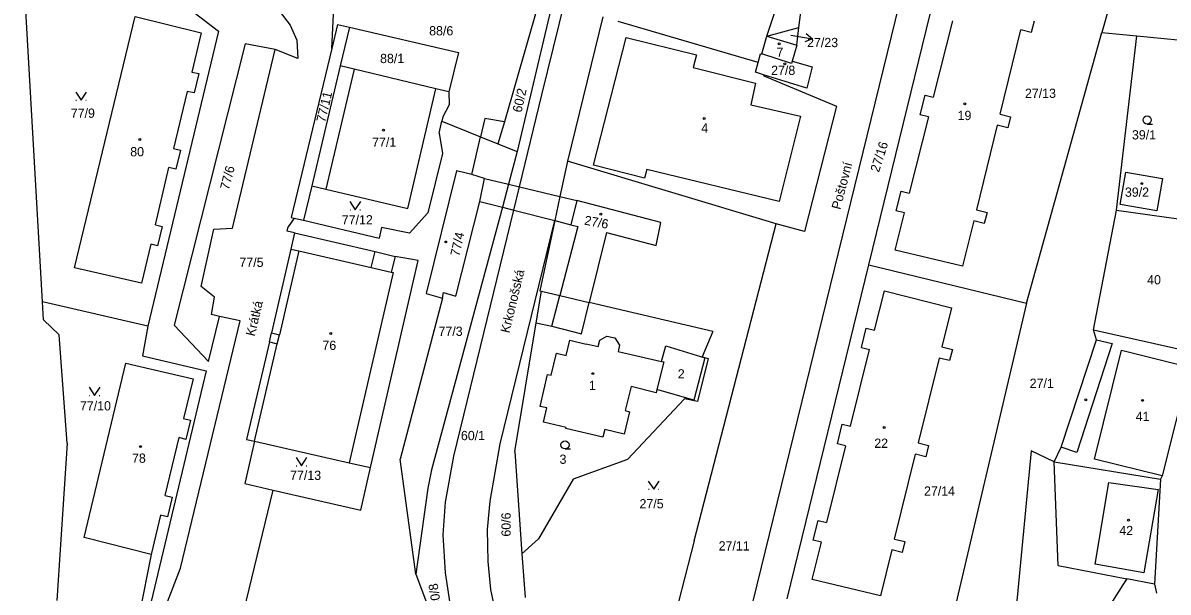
# Model space of a CAD drawing. Extents: x -670359 to -668019, y -978807 to -976674.
# Drawn here: x -670340.4 to -670130.3, y -977711.4 to -977606.8 of the extents above; entities that cross this region are included whole.
import ezdxf

# ---------------------------------------------------------------- set-up
doc = ezdxf.new("R2010")
doc.units = 0
for name, color, linetype in [('Hranice kat_území', 7, 'Continuous'), ('Hranice parcel', 7, 'Continuous'), ('Parcelní čísla', 7, 'Continuous'), ('Pop  PČ popisy', 7, 'Continuous'), ('Vnitřní kresba', 7, 'Continuous'), ('Značky budov', 7, 'Continuous'), ('Značky kultur', 7, 'Continuous')]:
    doc.layers.add(name, color=color, linetype=linetype)

msp = doc.modelspace()

# ---------------------------------------------------------------- linework, layer by layer
at = {"layer": 'Hranice kat_území'}
for points in [[(-670336.85, -977658.05), (-670340.44, -977594.85)], [(-670336.66, -977661.37), (-670336.85, -977658.05)], [(-670333.8, -977664.11), (-670336.66, -977661.37)], [(-670332.34, -977684.03), (-670333.8, -977664.11)], [(-670332.34, -977684.03), (-670334.21, -977712.94)]]:
    msp.add_lwpolyline(points, dxfattribs=at)
at = {"layer": 'Hranice parcel'}
for points in [[(-670249.31, -977636.91), (-670245.2, -977620.01), (-670240.92, -977602.66), (-670233.02, -977570.23), (-670231.23, -977562.51), (-670223.3, -977530.56), (-670219.23, -977513.75), (-670216.62, -977503.27), (-670213.37, -977489.17), (-670213.69, -977478.11)], [(-670163.89, -977539.01), (-670213.94, -977743.56)], [(-670203.93, -977609.27), (-670201.17, -977600.83), (-670198.43, -977589.2), (-670197.97, -977587.25)], [(-670185.19, -977651.24), (-670170.41, -977590.62)], [(-670198.01, -977607.66), (-670196.15, -977592.93)], [(-670139.52, -977598.15), (-670142.41, -977608.56)], [(-670283.76, -977611.51), (-670283.19, -977600.11)], [(-670311.4, -977603.07), (-670304.57, -977608.35)], [(-670293.42, -977604.61), (-670291.41, -977607.22)], [(-670245.98, -977603.86), (-670252.06, -977625.01)], [(-670243.58, -977604.27), (-670249.7, -977630.46)], [(-670330.99, -977651.81), (-670319.86, -977605.66)], [(-670319.86, -977605.66), (-670307.72, -977608.63)], [(-670291.41, -977607.22), (-670290.19, -977609.96)], [(-670282.7, -977607.08), (-670283.76, -977611.51)], [(-670282.7, -977607.08), (-670280.5, -977607.59)], [(-670280.5, -977607.59), (-670282.2, -977614.71)], [(-670280.5, -977607.59), (-670260.47, -977612.22)], [(-670233.99, -977605.7), (-670240.51, -977632.21)], [(-670205.49, -977614.1), (-670231.18, -977606.53)], [(-670203.93, -977609.27), (-670198.01, -977607.66)], [(-670198.42, -977610.91), (-670198.01, -977607.66)], [(-670169.86, -977606.42), (-670173.36, -977620.47)], [(-670154.87, -977606.52), (-670155.37, -977608.55)], [(-670304.57, -977608.35), (-670317.49, -977662.51)], [(-670307.72, -977608.63), (-670309.43, -977615.83)], [(-670204.8, -977612.5), (-670203.93, -977609.27)], [(-670203.93, -977609.27), (-670198.42, -977610.91)], [(-670161.11, -977623.58), (-670157.3, -977608.07)], [(-670155.37, -977608.55), (-670157.3, -977608.07)], [(-670156.24, -977658.3), (-670142.41, -977608.56)], [(-670142.41, -977608.56), (-670135.99, -977609.18)], [(-670139.74, -977641.23), (-670135.99, -977609.18)], [(-670135.99, -977609.18), (-670120.96, -977610.65)], [(-670301.97, -977644.5), (-670294.13, -977611.68)], [(-670289.99, -977613.35), (-670294.13, -977611.68)], [(-670283.76, -977611.51), (-670291.18, -977642.54)], [(-670290.19, -977609.96), (-670289.99, -977613.35)], [(-670198.42, -977610.91), (-670199.28, -977613.85)], [(-670260.47, -977612.22), (-670262.27, -977619.5)], [(-670205.49, -977614.1), (-670205.06, -977612.48)], [(-670205.06, -977612.48), (-670204.8, -977612.5)], [(-670199.4, -977614.26), (-670204.8, -977612.5)], [(-670199.28, -977613.85), (-670195.6, -977614.87), (-670196.57, -977618.81), (-670204.52, -977616.32)], [(-670199.28, -977613.85), (-670199.4, -977614.26)], [(-670309.43, -977615.83), (-670308.17, -977616.13)], [(-670282.2, -977614.71), (-670287.43, -977636.75)], [(-670279.63, -977615.33), (-670282.2, -977614.71)], [(-670264.66, -977618.94), (-670279.63, -977615.33)], [(-670204.52, -977616.32), (-670205.96, -977615.87), (-670205.49, -977614.1)], [(-670308.17, -977616.13), (-670309.02, -977619.68)], [(-670204.52, -977616.32), (-670204.46, -977616.54)], [(-670204.46, -977616.54), (-670191.14, -977622.08)], [(-670310.28, -977619.38), (-670312.79, -977629.87)], [(-670309.02, -977619.68), (-670310.28, -977619.38)], [(-670269.78, -977640.91), (-670264.66, -977618.94)], [(-670262.27, -977619.5), (-670264.66, -977618.94)], [(-670262.27, -977619.5), (-670262.23, -977621.89)], [(-670175.76, -977623.67), (-670174.87, -977620.1)], [(-670174.87, -977620.1), (-670173.36, -977620.47)], [(-670262.23, -977621.89), (-670263.37, -977624.05)], [(-670191.14, -977622.08), (-670196.99, -977645.15)], [(-670263.37, -977624.05), (-670263.56, -977624.87)], [(-670174.25, -977624.04), (-670177.76, -977638.11)], [(-670174.25, -977624.04), (-670175.76, -977623.67)], [(-670161.11, -977623.58), (-670159.18, -977624.06)], [(-670159.18, -977624.06), (-670159.68, -977626.09)], [(-670264.06, -977627.06), (-670263.56, -977624.87)], [(-670263.56, -977624.87), (-670256.44, -977627.73)], [(-670252.06, -977625.01), (-670253.29, -977629)], [(-670161.61, -977625.61), (-670165.43, -977641.15)], [(-670159.68, -977626.09), (-670161.61, -977625.61)], [(-670264.06, -977627.06), (-670263.45, -977630.78)], [(-670258.05, -977634.65), (-670256.44, -977627.73)], [(-670256.44, -977627.73), (-670253.29, -977629)], [(-670312.79, -977629.87), (-670311.52, -977630.18)], [(-670311.52, -977630.18), (-670312.36, -977633.7)], [(-670263.45, -977630.78), (-670266.1, -977641.73)], [(-670253.29, -977629), (-670249.7, -977630.46)], [(-670249.7, -977630.46), (-670251.31, -977636.43)], [(-670240.51, -977632.21), (-670241.88, -977638.68)], [(-670202.18, -977643.75), (-670240.51, -977632.21)], [(-670316.13, -977643.91), (-670313.63, -977633.4)], [(-670312.36, -977633.7), (-670313.63, -977633.4)], [(-670260.84, -977633.99), (-670266.45, -977656.5)], [(-670258.05, -977634.65), (-670260.84, -977633.99)], [(-670255.73, -977635.38), (-670258.05, -977634.65)], [(-670132.33, -977641.31), (-670139.05, -977640.15), (-670138.03, -977634.22), (-670131.31, -977635.37), (-670132.33, -977641.31)], [(-670287.43, -977636.75), (-670288.94, -977643.07)], [(-670287.43, -977636.75), (-670284.82, -977637.36)], [(-670256.56, -977639.61), (-670255.73, -977635.38)], [(-670251.31, -977636.43), (-670252.45, -977640.66)], [(-670250.36, -977641.2), (-670249.31, -977636.91)], [(-670284.82, -977637.36), (-670269.78, -977640.91)], [(-670241.88, -977638.68), (-670242.83, -977643.13)], [(-670180.16, -977641.34), (-670179.27, -977637.73)], [(-670179.27, -977637.73), (-670177.76, -977638.11)], [(-670252.45, -977640.66), (-670265.48, -977688.9)], [(-670228.39, -977798.54), (-670235.68, -977780.88), (-670248.21, -977752.09), (-670257.66, -977728.06), (-670261.88, -977714.27), (-670262.87, -977707.81), (-670263.3, -977700.83), (-670262.9, -977694.87), (-670261.36, -977686.41), (-670250.36, -977641.2)], [(-670261.01, -977657.02), (-670256.56, -977639.61)], [(-670238.8, -977639.42), (-670239.87, -977643.89)], [(-670223.38, -977643.45), (-670238.8, -977639.42)], [(-670165.43, -977641.15), (-670163.5, -977641.63)], [(-670143.98, -977663.19), (-670139.74, -977641.23)], [(-670139.74, -977641.23), (-670121.83, -977643.75)], [(-670290.67, -977642.66), (-670291.73, -977644.25)], [(-670291.18, -977642.54), (-670290.67, -977642.66)], [(-670290.67, -977642.66), (-670288.94, -977643.07)], [(-670288.94, -977643.07), (-670275.07, -977646.34)], [(-670266.1, -977641.73), (-670269.49, -977645.42)], [(-670183.39, -977889.81), (-670193.56, -977862.25), (-670201.26, -977845.22), (-670205.62, -977834.5), (-670231.98, -977771.32), (-670242.71, -977745.05), (-670249.53, -977728.04), (-670253.85, -977714.41), (-670254.54, -977710.9), (-670255.07, -977705.75), (-670255.17, -977699.87), (-670254.7, -977694.67), (-670252.82, -977684.15), (-670242.83, -977643.13)], [(-670242.83, -977643.13), (-670245.56, -977656.01)], [(-670180.36, -977648.54), (-670178.66, -977641.71)], [(-670178.66, -977641.71), (-670180.16, -977641.34)], [(-670165.93, -977643.16), (-670167.98, -977651.51)], [(-670164, -977643.64), (-670165.93, -977643.16)], [(-670163.5, -977641.63), (-670164, -977643.64)], [(-670316.13, -977643.91), (-670314.87, -977644.21)], [(-670314.87, -977644.21), (-670315.71, -977647.74)], [(-670307.73, -977655.25), (-670305.41, -977644.71)], [(-670305.41, -977644.71), (-670301.97, -977644.5)], [(-670291.96, -977645.08), (-670291.73, -977644.25)], [(-670290.58, -977645.39), (-670291.96, -977645.08)], [(-670290.58, -977645.39), (-670291.25, -977648.36)], [(-670290.58, -977645.39), (-670275.82, -977648.8)], [(-670274.62, -977644.41), (-670275.07, -977646.34)], [(-670269.49, -977645.42), (-670274.62, -977644.41)], [(-670238.59, -977644.22), (-670241.89, -977656.87)], [(-670239.87, -977643.89), (-670238.59, -977644.22)], [(-670233.32, -977645.3), (-670236.5, -977658.15)], [(-670233.32, -977645.3), (-670224.21, -977647.68)], [(-670224.21, -977647.68), (-670223.38, -977643.45)], [(-670217.24, -977701.95), (-670202.18, -977643.75)], [(-670196.99, -977645.15), (-670202.18, -977643.75)], [(-670316.98, -977647.44), (-670318.69, -977654.62)], [(-670315.71, -977647.74), (-670316.98, -977647.44)], [(-670291.25, -977648.36), (-670294.8, -977663.76)], [(-670275.82, -977648.8), (-670272.15, -977649.75)], [(-670167.98, -977651.51), (-670180.36, -977648.54)], [(-670318.69, -977654.62), (-670330.99, -977651.81)], [(-670276.65, -977688.5), (-670267.91, -977650.48)], [(-670267.91, -977650.48), (-670272.15, -977649.75)], [(-670200.15, -977712.62), (-670185.19, -977651.24)], [(-670185.19, -977651.24), (-670156.24, -977658.3)], [(-670305.26, -977657.19), (-670307.73, -977655.25)], [(-670245.56, -977656.01), (-670245.27, -977656.08)], [(-670184.14, -977663.25), (-670182.34, -977656.05)], [(-670182.34, -977656.05), (-670170.04, -977659.17)], [(-670317.49, -977662.51), (-670336.85, -977658.05)], [(-670305.85, -977660.38), (-670305.26, -977657.19)], [(-670263.41, -977657.4), (-670271.23, -977686.94)], [(-670266.45, -977656.5), (-670263.41, -977657.4)], [(-670263.41, -977657.4), (-670263.25, -977656.36)], [(-670263.25, -977656.36), (-670261.01, -977657.02)], [(-670246.24, -977661.92), (-670245.27, -977656.08)], [(-670245.27, -977656.08), (-670241.89, -977656.87)], [(-670241.89, -977656.87), (-670236.5, -977658.15)], [(-670213.84, -977663.51), (-670236.5, -977658.15)], [(-670170.04, -977659.17), (-670171.8, -977666.33)], [(-670156.24, -977658.3), (-670170.72, -977719.8)], [(-670311.54, -977706.97), (-670300.57, -977661.54)], [(-670304.33, -977660.72), (-670305.85, -977660.38)], [(-670300.57, -977661.54), (-670304.33, -977660.72)], [(-670250.17, -977685.57), (-670246.24, -977661.92)], [(-670317.49, -977662.51), (-670318.48, -977667.94)], [(-670295.18, -977665.42), (-670294.8, -977663.76)], [(-670243.48, -977671.53), (-670242.54, -977667.45), (-670240.74, -977667.89), (-670240.06, -977665.12), (-670237.08, -977665.83), (-670237.04, -977665.74), (-670234.84, -977666.26), (-670234.56, -977665.11), (-670233.29, -977664.36), (-670231.78, -977664.68), (-670230.92, -977665.98), (-670231.22, -977667.17)], [(-670213.84, -977663.51), (-670215.8, -977668.13)], [(-670186.54, -977666.45), (-670185.65, -977662.87)], [(-670185.65, -977662.87), (-670184.14, -977663.25)], [(-670143.98, -977663.19), (-670125.68, -977667.32)], [(-670143.43, -977665.04), (-670143.98, -977663.19)], [(-670295.18, -977665.42), (-670299.39, -977683.32)], [(-670222.45, -977666.15), (-670215.31, -977668.34), (-670217.32, -977676.12), (-670224.09, -977674.18)], [(-670223.22, -977669), (-670222.45, -977666.15)], [(-670186.54, -977666.45), (-670185.04, -977666.83)], [(-670171.8, -977666.33), (-670169.86, -977666.81)], [(-670149.9, -977684.75), (-670143.43, -977665.04)], [(-670318.48, -977667.94), (-670306.8, -977670.72)], [(-670231.22, -977667.17), (-670223.22, -977669)], [(-670214.68, -977668.46), (-670216.66, -977676.36)], [(-670215.8, -977668.13), (-670214.68, -977668.46)], [(-670188.55, -977680.88), (-670185.04, -977666.83)], [(-670172.3, -977668.37), (-670176.15, -977683.96)], [(-670170.36, -977668.85), (-670172.3, -977668.37)], [(-670169.86, -977666.81), (-670170.36, -977668.85)], [(-670329.19, -977701.33), (-670321.52, -977669.31)], [(-670321.52, -977669.31), (-670309.21, -977672.2)], [(-670306.8, -977670.72), (-670317.87, -977717.22)], [(-670223.22, -977669), (-670222.81, -977669.1), (-670224.09, -977674.18)], [(-670126.34, -977670.04), (-670131.37, -977689.99)], [(-670309.21, -977672.2), (-670310.94, -977679.47)], [(-670233.99, -977682.88), (-670240.77, -977681.29), (-670240.76, -977681.15), (-670244.91, -977680.15), (-670244.26, -977677.53), (-670245.51, -977677.25), (-670244.15, -977671.37), (-670243.48, -977671.53)], [(-670224.09, -977674.18), (-670224.23, -977674.74), (-670228.82, -977673.63), (-670229.89, -977678.04), (-670229.1, -977678.24)], [(-670219.05, -977675.87), (-670229.46, -977686.99)], [(-670216.66, -977676.36), (-670219.05, -977675.87)], [(-670229.1, -977678.24), (-670230.12, -977682.35), (-670233.64, -977681.52), (-670233.99, -977682.88)], [(-670310.94, -977679.47), (-670309.66, -977679.77)], [(-670309.66, -977679.77), (-670310.51, -977683.31)], [(-670190.96, -977684.11), (-670190.06, -977680.5)], [(-670190.06, -977680.5), (-670188.55, -977680.88)], [(-670314.32, -977693.65), (-670311.78, -977683)], [(-670310.51, -977683.31), (-670311.78, -977683)], [(-670299.39, -977683.32), (-670297.92, -977683.65)], [(-670297.92, -977683.65), (-670299.73, -977691.42)], [(-670297.92, -977683.65), (-670280.54, -977687.61)], [(-670189.46, -977684.49), (-670192.99, -977698.61)], [(-670189.46, -977684.49), (-670190.96, -977684.11)], [(-670176.15, -977683.96), (-670174.21, -977684.44)], [(-670174.21, -977684.44), (-670174.71, -977686.5)], [(-670155.4, -977685.45), (-670163.47, -977770.05)], [(-670151.2, -977687.46), (-670155.4, -977685.45)], [(-670151.2, -977687.46), (-670149.9, -977684.75)], [(-670268.34, -977708.07), (-670271.23, -977686.94)], [(-670250.17, -977685.57), (-670248.85, -977704.32)], [(-670229.46, -977686.99), (-670239.48, -977690.6)], [(-670180.5, -977701.62), (-670176.65, -977686.02)], [(-670174.71, -977686.5), (-670176.65, -977686.02)], [(-670151.2, -977687.46), (-670131.69, -977690.63)], [(-670150.45, -977706.5), (-670151.2, -977687.46)], [(-670280.54, -977687.61), (-670276.65, -977688.5)], [(-670278.44, -977696.31), (-670276.65, -977688.5)], [(-670265.48, -977688.9), (-670266.14, -977692.25)], [(-670299.73, -977691.42), (-670294.49, -977692.62)], [(-670239.48, -977690.6), (-670245.8, -977701.59)], [(-670131.69, -977690.63), (-670132.79, -977709.9)], [(-670131.37, -977689.99), (-670131.69, -977690.63)], [(-670314.32, -977693.65), (-670313.04, -977693.96)], [(-670299.92, -977714.89), (-670294.49, -977692.62)], [(-670294.49, -977692.62), (-670278.44, -977696.31)], [(-670266.14, -977692.25), (-670268.34, -977708.07)], [(-670313.04, -977693.96), (-670313.89, -977697.52)], [(-670315.16, -977697.22), (-670316.89, -977704.46)], [(-670313.89, -977697.52), (-670315.16, -977697.22)], [(-670195.4, -977701.83), (-670194.5, -977698.24)], [(-670194.5, -977698.24), (-670192.99, -977698.61)], [(-670316.89, -977704.46), (-670329.19, -977701.33)], [(-670245.8, -977701.59), (-670248.85, -977704.32)], [(-670217.24, -977701.95), (-670221.85, -977719.84)], [(-670195.6, -977709.06), (-670193.89, -977702.2)], [(-670193.89, -977702.2), (-670195.4, -977701.83)], [(-670180.5, -977701.62), (-670178.56, -977702.1)], [(-670178.56, -977702.1), (-670179.05, -977704.1)], [(-670248.85, -977704.32), (-670248.28, -977712.37)], [(-670180.99, -977703.63), (-670183.06, -977712.03)], [(-670179.05, -977704.1), (-670180.99, -977703.63)], [(-670317.01, -977721.25), (-670311.54, -977706.97)], [(-670268.34, -977708.07), (-670252.01, -977751.62)], [(-670150.45, -977706.5), (-670137.86, -977708.92)], [(-670183.06, -977712.03), (-670195.6, -977709.06)], [(-670138.55, -977710.02), (-670143.55, -977717.86)], [(-670137.86, -977708.92), (-670138.55, -977710.02)], [(-670132.79, -977709.9), (-670137.86, -977708.92)], [(-670132.79, -977709.9), (-670132.4, -977711.58)]]:
    msp.add_lwpolyline(points, dxfattribs=at)
at = {"layer": 'Parcelní čísla'}
msp.add_line((-670196.69, -977608.78), (-670195.54, -977609.74), dxfattribs=at)
msp.add_lwpolyline([(-670199.48, -977609.06), (-670195.54, -977609.74), (-670196.95, -977610.26)], dxfattribs=at)
at = {"layer": 'Vnitřní kresba'}
for points in [[(-670235.71, -977632.96), (-670229.7, -977609.49)], [(-670229.7, -977609.49), (-670216.84, -977612.7)], [(-670299.65, -977610.68), (-670312.66, -977662.34)], [(-670294.13, -977611.68), (-670299.65, -977610.68)], [(-670216.84, -977612.7), (-670217.41, -977615.01)], [(-670279.63, -977615.33), (-670284.82, -977637.36)], [(-670217.41, -977615.01), (-670205.99, -977617.89)], [(-670205.99, -977617.89), (-670206.82, -977621.89)], [(-670206.82, -977621.89), (-670197.71, -977623.95)], [(-670255.65, -977624.35), (-670256.44, -977627.73)], [(-670252.06, -977625.01), (-670255.65, -977624.35)], [(-670197.71, -977623.95), (-670201.67, -977639.6)], [(-670226.36, -977635.35), (-670235.71, -977632.96)], [(-670225.95, -977633.75), (-670226.36, -977635.35)], [(-670201.67, -977639.6), (-670225.95, -977633.75)], [(-670255.73, -977635.38), (-670251.31, -977636.43)], [(-670251.31, -977636.43), (-670249.31, -977636.91)], [(-670249.31, -977636.91), (-670241.88, -977638.68)], [(-670241.88, -977638.68), (-670238.8, -977639.42)], [(-670256.56, -977639.61), (-670252.45, -977640.66)], [(-670252.45, -977640.66), (-670250.36, -977641.2)], [(-670250.36, -977641.2), (-670242.83, -977643.13)], [(-670242.83, -977643.13), (-670239.87, -977643.89)], [(-670289.82, -977648.69), (-670293.37, -977664.09)], [(-670291.25, -977648.36), (-670289.82, -977648.69)], [(-670289.82, -977648.69), (-670276.51, -977651.76)], [(-670276.51, -977651.76), (-670275.82, -977648.8)], [(-670276.51, -977651.76), (-670272.83, -977652.61)], [(-670272.15, -977649.75), (-670272.83, -977652.61)], [(-670272.51, -977652.68), (-670280.54, -977687.61)], [(-670272.83, -977652.61), (-670272.51, -977652.68)], [(-670243.36, -977662.5), (-670241.89, -977656.87)], [(-670237.93, -977663.9), (-670236.5, -977658.15)], [(-670312.66, -977662.34), (-670306.39, -977669.02)], [(-670306.39, -977669.02), (-670304.33, -977660.72)], [(-670246.24, -977661.92), (-670243.36, -977662.5)], [(-670294.8, -977663.76), (-670293.37, -977664.09)], [(-670293.75, -977665.75), (-670293.37, -977664.09)], [(-670243.36, -977662.5), (-670237.93, -977663.9)], [(-670297.92, -977683.65), (-670293.75, -977665.75)], [(-670295.18, -977665.42), (-670293.75, -977665.75)], [(-670140.56, -977665.7), (-670147.02, -977685.73)], [(-670143.43, -977665.04), (-670140.56, -977665.7)], [(-670143.75, -977686.95), (-670138.8, -977666.91)], [(-670138.8, -977666.91), (-670126.34, -977670.04)], [(-670147.02, -977685.73), (-670149.9, -977684.75)], [(-670131.37, -977689.99), (-670143.75, -977686.95)], [(-670143.65, -977706.22), (-670141.14, -977691.21)], [(-670141.14, -977691.21), (-670132.11, -977692.55)], [(-670132.11, -977692.55), (-670134.7, -977707.81)], [(-670316.89, -977704.46), (-670319.04, -977715.24)], [(-670134.7, -977707.81), (-670143.65, -977706.22)]]:
    msp.add_lwpolyline(points, dxfattribs=at)
at = {"layer": 'Značky budov'}
for centre in [(-670201.63, -977610.64), (-670200.6, -977614.33), (-670167.56, -977621.66), (-670215.41, -977624.37), (-670274.24, -977626.5), (-670318.99, -977628.22), (-670135.11, -977636.34), (-670234.37, -977641.96), (-670262.85, -977647.05), (-670283.95, -977663.86), (-670235.83, -977671.24), (-670134.96, -977676.15), (-670182.38, -977681.12), (-670318.86, -977684.65), (-670137.53, -977698.15)]:
    msp.add_circle(centre, 0.175, dxfattribs=at)
at = {"layer": 'Značky kultur'}
for p, q in [((-670330.7, -977621.03), (-670330.6, -977621.03)), ((-670328.9, -977621.03), (-670328.8, -977621.03)), ((-670134.1, -977625.39), (-670133.1, -977625.39)), ((-670280.4, -977641.14), (-670280.3, -977641.14)), ((-670278.6, -977641.14), (-670278.5, -977641.14)), ((-670328.24, -977675.23), (-670328.14, -977675.23)), ((-670326.44, -977675.23), (-670326.34, -977675.23)), ((-670240.95, -977685.08), (-670239.95, -977685.08)), ((-670290.26, -977688.16), (-670290.16, -977688.16)), ((-670288.46, -977688.16), (-670288.36, -977688.16)), ((-670225.61, -977692.49), (-670225.51, -977692.49)), ((-670223.81, -977692.49), (-670223.71, -977692.49))]:
    msp.add_line(p, q, dxfattribs=at)
for points in [[(-670330.75, -977619.53), (-670329.75, -977621.03), (-670328.75, -977619.53)], [(-670280.45, -977639.64), (-670279.45, -977641.14), (-670278.45, -977639.64)], [(-670328.29, -977673.73), (-670327.29, -977675.23), (-670326.29, -977673.73)], [(-670290.31, -977686.66), (-670289.31, -977688.16), (-670288.31, -977686.66)], [(-670225.66, -977690.99), (-670224.66, -977692.49), (-670223.66, -977690.99)]]:
    msp.add_lwpolyline(points, dxfattribs=at)
for centre, radius in [((-670201.63, -977610.64), 0.175), ((-670200.6, -977614.33), 0.175), ((-670167.56, -977621.66), 0.175), ((-670215.41, -977624.37), 0.175), ((-670134.1, -977624.64), 0.75), ((-670274.24, -977626.5), 0.175), ((-670318.99, -977628.22), 0.175), ((-670135.11, -977636.34), 0.175), ((-670234.37, -977641.96), 0.175), ((-670262.85, -977647.05), 0.175), ((-670283.95, -977663.86), 0.175), ((-670235.83, -977671.24), 0.175), ((-670145.39, -977676.04), 0.175), ((-670134.96, -977676.15), 0.175), ((-670182.38, -977681.12), 0.175), ((-670318.86, -977684.65), 0.175), ((-670240.95, -977684.33), 0.75), ((-670137.53, -977698.15), 0.175)]:
    msp.add_circle(centre, radius, dxfattribs=at)

# ---------------------------------------------------------------- texts
at = {"layer": 'Parcelní čísla'}
for s, height, p in [('88/6', 1.7, (-670265.88, -977609.1)), ('27/23', 0.1, (-670199.48, -977609.06)), ('27/23', 1.7, (-670196.52, -977611.26)), ('7', 1.7, (-670202.13, -977613.03)), ('88/1', 1.7, (-670274.89, -977614.19)), ('27/8', 1.7, (-670203.12, -977616.37)), ('27/13', 1.7, (-670156.54, -977620.59)), ('77/9', 1.7, (-670331.65, -977624.24)), ('19', 1.7, (-670168.9, -977624.66)), ('4', 1.7, (-670215.95, -977626.97)), ('39/1', 1.7, (-670136.9, -977628.22)), ('77/1', 1.7, (-670276.35, -977629.57)), ('80', 1.7, (-670320.74, -977631.32)), ('39/2', 1.7, (-670138.19, -977638.75)), ('77/12', 1.7, (-670281.92, -977643.83)), ('77/5', 1.7, (-670300.7, -977651.64)), ('40', 1.7, (-670134.11, -977654.84)), ('77/3', 1.7, (-670264.16, -977664.31)), ('76', 1.7, (-670285.47, -977666.89)), ('2', 1.7, (-670220.25, -977672.13)), ('1', 1.7, (-670236.56, -977674.25)), ('27/1', 1.7, (-670155.67, -977673.86)), ('77/10', 1.7, (-670329.97, -977678)), ('41', 1.7, (-670136.21, -977679.94)), ('60/1', 1.7, (-670260.05, -977683.46)), ('22', 1.7, (-670184.19, -977684.87)), ('78', 1.7, (-670320.41, -977687.62)), ('3', 1.7, (-670241.95, -977687.81)), ('77/13', 1.7, (-670291.4, -977690.76)), ('27/14', 1.7, (-670175.06, -977693.65)), ('27/5', 1.7, (-670227.28, -977695.99)), ('42', 1.7, (-670139.22, -977700.91)), ('27/11', 1.7, (-670212.75, -977703.73))]:
    msp.add_text(s, height=height, dxfattribs=at).set_placement(p)
for s, rotation, p in [('77/11', 76.7837, (-670284.96, -977625.18)), ('60/2', 77.511, (-670248.94, -977623.37)), ('27/16', 72.392, (-670183.34, -977634.37)), ('77/6', 75.3356, (-670302.65, -977637.6)), ('27/6', 349.5489, (-670237.5, -977643.85)), ('77/4', 77.4825, (-670260.36, -977649.79)), ('60/6', 90, (-670250.92, -977701.18)), ('60/8', 99.1577, (-670263.65, -977714.04))]:
    msp.add_text(s, height=1.7, rotation=rotation, dxfattribs=at).set_placement(p)
at = {"layer": 'Pop  PČ popisy'}
for s, rotation, p in [('Poštovní', 75.4096, (-670190.42, -977641.21)), ('Krkonošská', 76.4071, (-670251.17, -977663.89)), ('Krátká', 76.5396, (-670297.9, -977664.48))]:
    msp.add_text(s, height=1.7, rotation=rotation, dxfattribs=at).set_placement(p)

doc.saveas('drawing.dxf')
